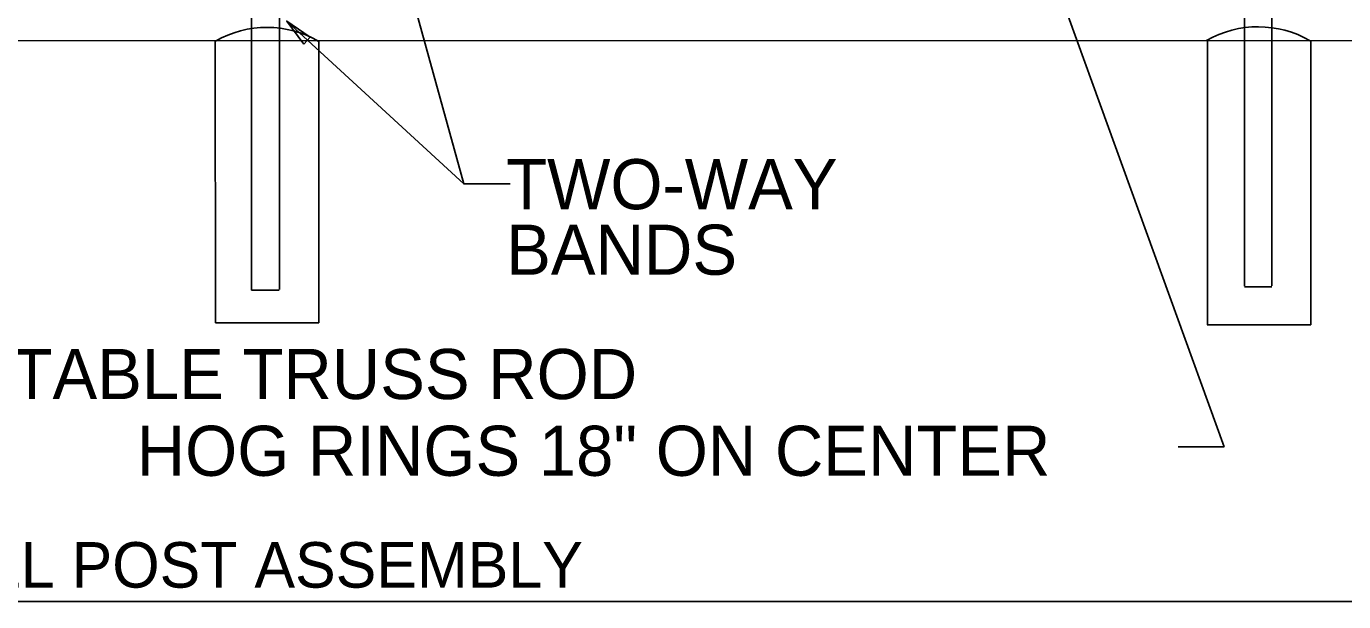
# Model space of a CAD drawing. Extents: x 0 to 1270, y 0 to 830.
# Drawn here: x 613.6 to 742.4, y 322.9 to 379.2 of the extents above; entities that cross this region are included whole.
import ezdxf

# ---------------------------------------------------------------- set-up
doc = ezdxf.new("R2010")
doc.units = 0
for name, color, linetype in [('CT_CSHT_GeneralLabel', 7, 'Continuous'), ('CT_Dimensions', 7, 'Continuous'), ('sb_Chainlink Fence', 7, 'Continuous'), ('sb_Existing Concrete', 7, 'Continuous'), ('sb_Existing Structural Steel', 7, 'Continuous')]:
    doc.layers.add(name, color=color, linetype=linetype)

msp = doc.modelspace()

# ---------------------------------------------------------------- linework, layer by layer
at = {"layer": 'CT_Dimensions'}
msp.add_line((441.85, 322.9), (831.47, 322.9), dxfattribs=at)
at = {"layer": 'sb_Chainlink Fence'}
for p, q in [((656.36, 363.76), (638.49, 428.26)), ((730.7, 338.04), (704.2, 411.29)), ((656.36, 363.76), (639.06, 379.65)), ((524.25, 377.77), (832.13, 377.79)), ((660.87, 363.76), (656.36, 363.76)), ((730.7, 338.04), (726.19, 338.04))]:
    msp.add_line(p, q, dxfattribs=at)
msp.add_lwpolyline([(640.69, 377.45), (639.03, 379.69), (641.33, 378.11)], close=True, dxfattribs=at)
at = {"layer": 'sb_Existing Concrete'}
for p, q in [((632.06, 350.18), (632.05, 377.75)), ((642.17, 350.18), (642.16, 377.71)), ((729.06, 349.97), (729.06, 377.72)), ((739.16, 349.99), (739.16, 377.8)), ((632.06, 350.18), (642.17, 350.18)), ((729.05, 349.99), (739.18, 349.99))]:
    msp.add_line(p, q, dxfattribs=at)
for centre in [(637.08, 368.93), (734.01, 368.99)]:
    msp.add_arc(centre, 10.15, 59.953, 119.6876, dxfattribs=at)
at = {"layer": 'sb_Existing Structural Steel'}
for p, q in [((635.6, 378.94), (635.6, 438.49)), ((638.31, 378.97), (638.31, 438.51)), ((732.7, 378.84), (732.7, 433.44)), ((735.35, 378.81), (735.35, 433.54)), ((635.6, 353.36), (635.6, 378.94)), ((638.31, 353.44), (638.31, 378.97)), ((732.7, 353.75), (732.7, 378.84)), ((735.35, 353.79), (735.35, 378.81)), ((635.6, 353.36), (638.28, 353.36)), ((732.68, 353.71), (735.35, 353.71))]:
    msp.add_line(p, q, dxfattribs=at)

# ---------------------------------------------------------------- texts
at = {"layer": 'CT_CSHT_GeneralLabel'}
msp.add_text('PULL POST ASSEMBLY', height=4.455, dxfattribs=at).set_placement((601.44, 324.27))
at = {"layer": 'CT_Dimensions'}
for s, height, p in [('TWO-WAY ', 4.901, (660.49, 361.29)), ('BANDS', 4.901, (660.49, 354.88)), ("…'' DIA. ADJUSTABLE TRUSS ROD", 4.9005, (565.2, 342.72)), ('HOG RINGS 18" ON CENTER', 4.9005, (624.36, 335.21))]:
    msp.add_text(s, height=height, dxfattribs=at).set_placement(p)

doc.saveas('drawing.dxf')
